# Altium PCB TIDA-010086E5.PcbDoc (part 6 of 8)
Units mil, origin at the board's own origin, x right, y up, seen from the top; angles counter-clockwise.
Board outline 6400 x 6200 mil, 6 copper layers (Top Layer, Power, AGND, Signal, PGND, Bottom Layer), stack 70.536 mil thick; 717 components, 376 nets, 2259 pads, 2183 vias.
Unrouted connection lines stored in the file: 1424.
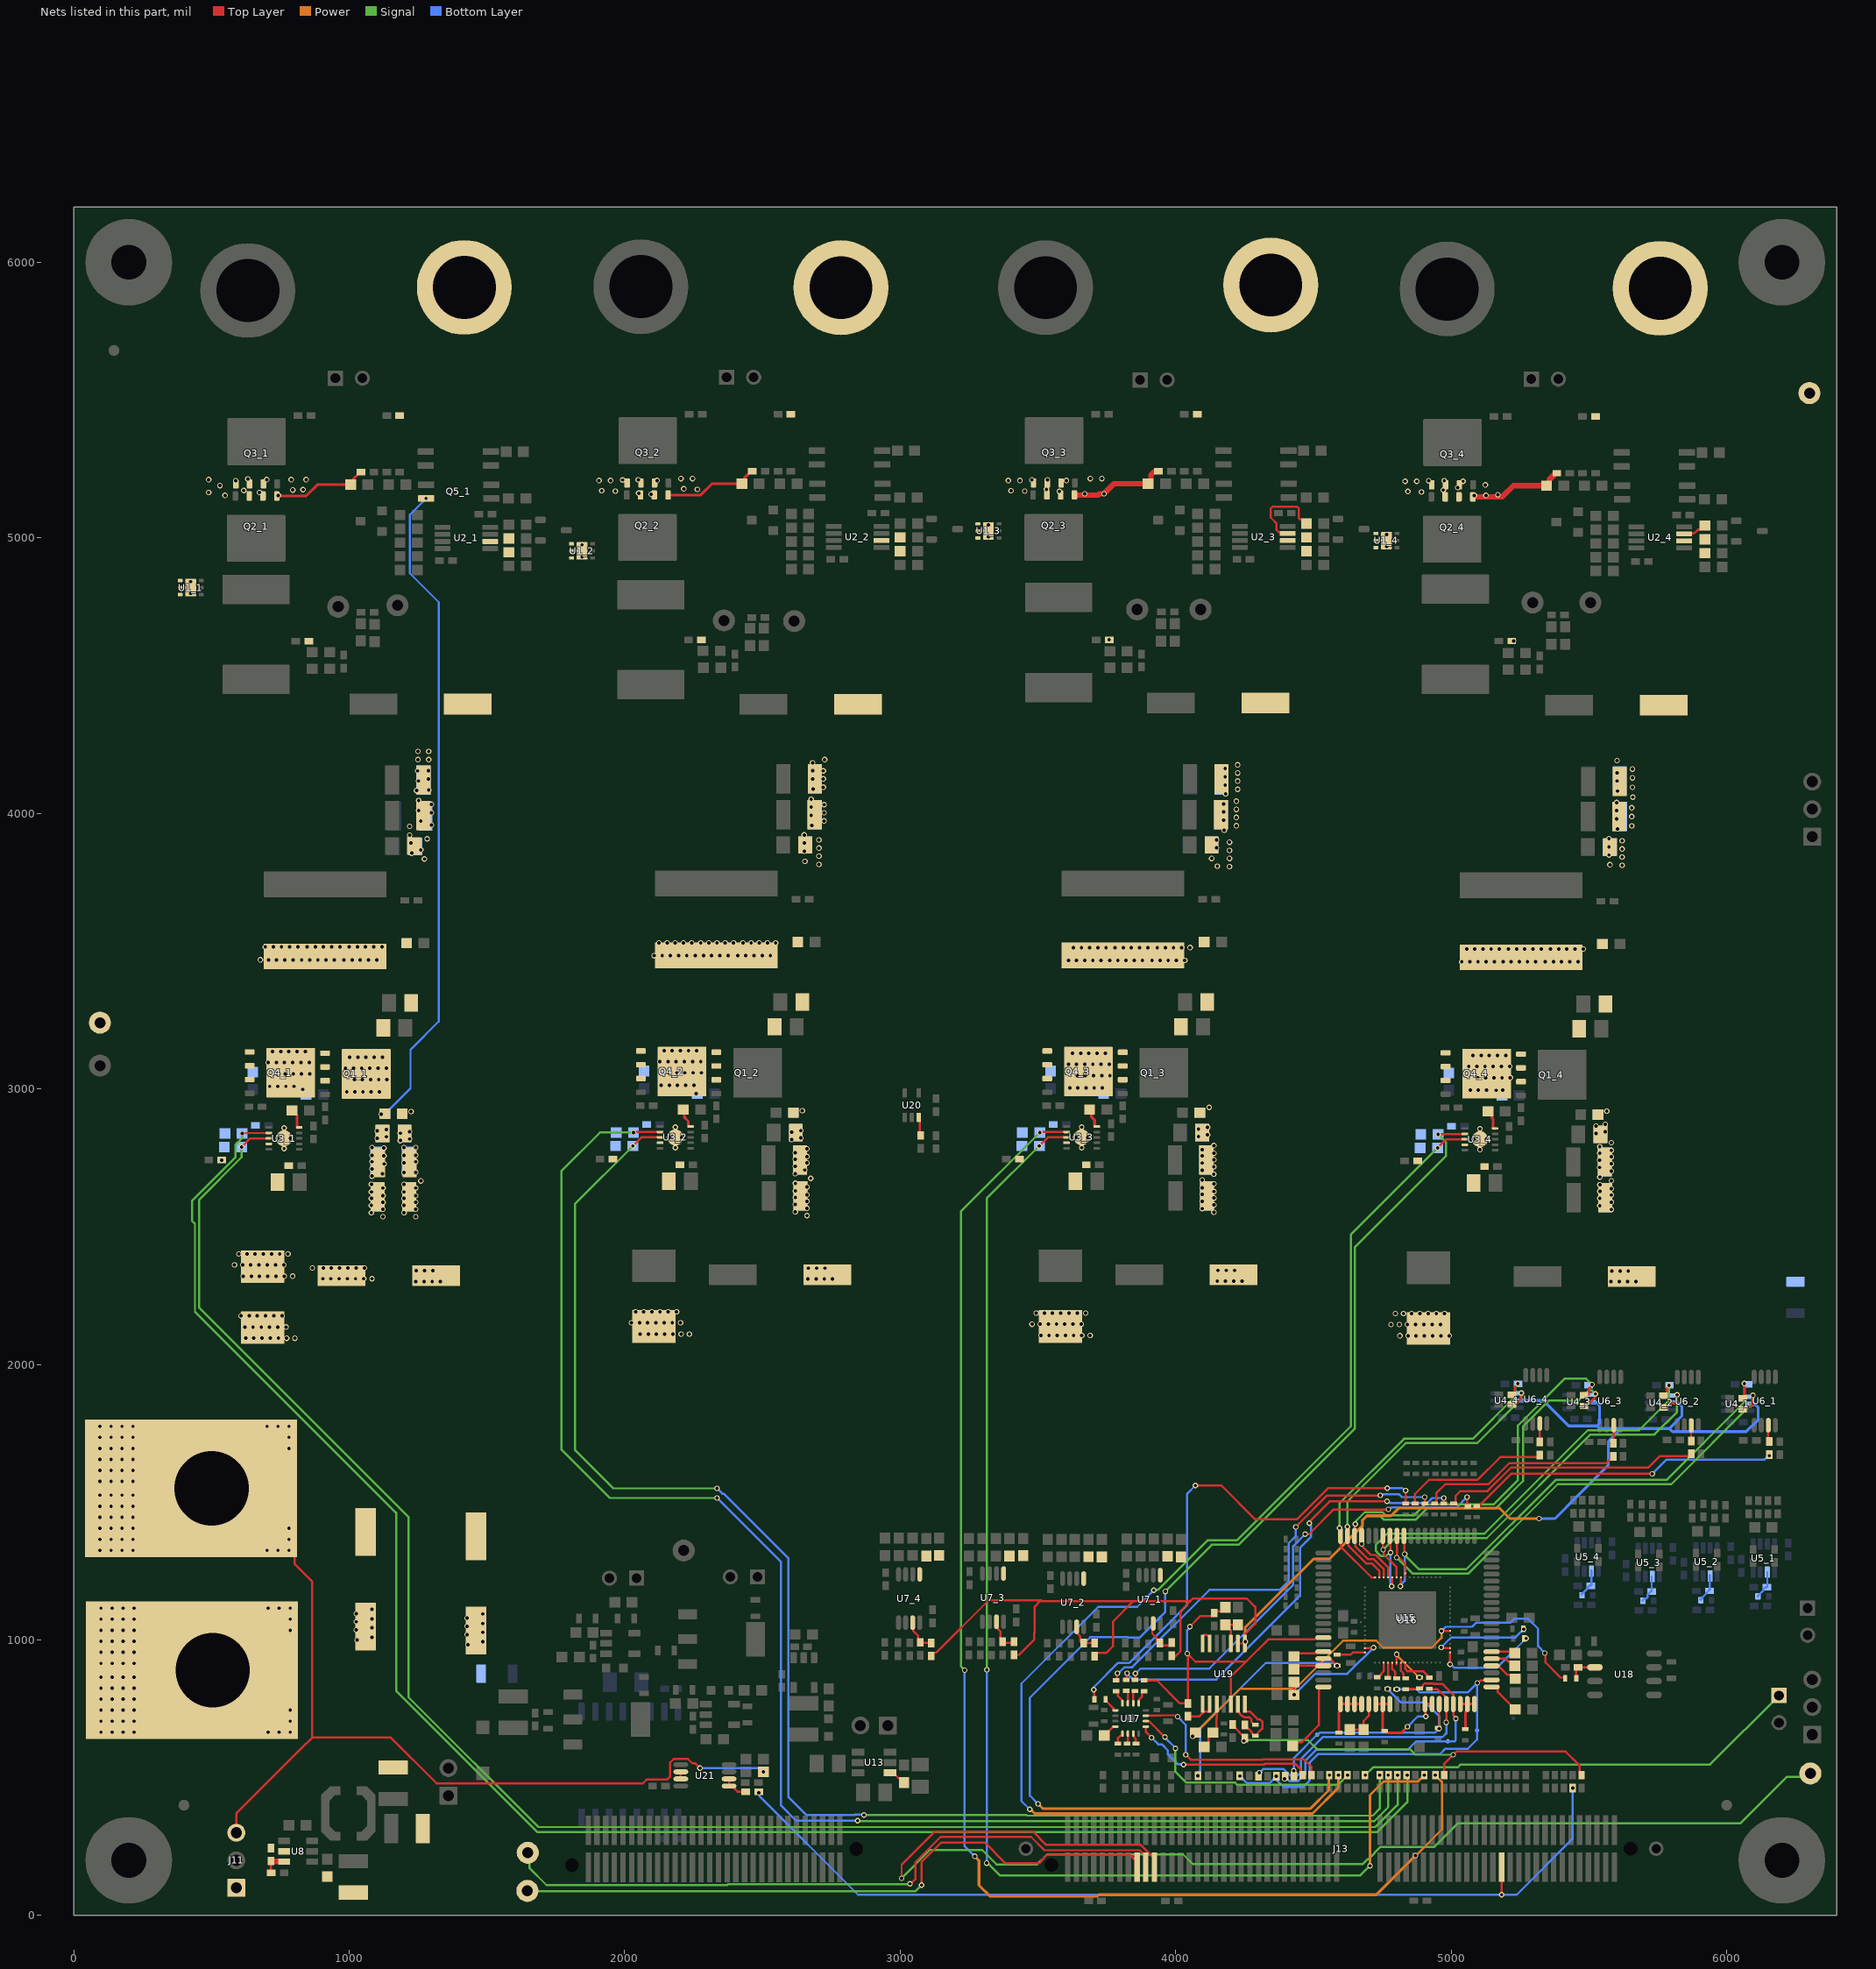
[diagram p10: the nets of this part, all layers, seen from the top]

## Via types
v1: diameter 20, hole 12.5, Top Layer to Bottom Layer, 1408 vias
v2: diameter 20, hole 12, Top Layer to Bottom Layer, tented both sides, 775 vias

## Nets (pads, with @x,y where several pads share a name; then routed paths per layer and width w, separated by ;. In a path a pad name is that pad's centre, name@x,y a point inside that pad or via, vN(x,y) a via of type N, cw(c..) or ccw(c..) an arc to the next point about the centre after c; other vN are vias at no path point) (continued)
NetR25_3_2: R25_3.2 U2_3.7 | length 311.6
  Top Layer w7.87: U2_3.7@4406.37,5015.63 4386.69,5015.63 4381.76,5020.55 4377.15,5020.55 4374.08,5020.55 4366.02,5028.61 4366.02,5051.52 4344.59,5072.94 4344.59,5106.35 4351.51,5113.27 4440.03,5113.27 4446.95,5106.35 4446.95,5070.72 4451.56,5066.1 4459.71,5066.1 R25_3.2@4474.47,5051.34
NetR25_4_2: R25_4.2 U2_4.7 | length 87.3
  Top Layer w7.87: U2_4.7@5845.27,5014.68 5858.04,5014.68 5858.67,5015.31 5881.01,5015.31 5895.56,5029.86 5905.61,5029.86 R25_4.2@5920.25,5044.5
NetR28_1_1: R28_1.1 R30_1.2 U2_1.6
NetR28_2_1: R28_2.1 R30_2.2 U2_2.6
NetR28_3_1: R28_3.1 R30_3.2 U2_3.6
NetR28_4_1: R28_4.1 R30_4.2 U2_4.6
NetR36_1_1: R36_1.1 R38_1.2 U5_1.6 | length 104.1
  Bottom Layer w7.87: R38_1.2@6113.13,1158.12 6113.13,1160.09 6134.51,1181.47 6134.51,1184.94 6141.32,1191.75 R36_1.1@6145.26,1191.75 6147.22,1193.72 U5_1.6@6147.22,1245.76
NetR36_2_1: R36_2.1 R38_2.2 U5_2.6 | length 102.9
  Bottom Layer w7.87: R38_2.2@5903.68,1146.83 5905.65,1146.83 5911.01,1152.19 5911.01,1154.16 5925.42,1168.57 5925.42,1170.07 5937.77,1182.42 U5_2.6@5937.77,1234.47
NetR36_3_1: R36_3.1 R38_3.2 U5_3.6 | length 106.6
  Bottom Layer w7.87: R38_3.2@5695.19,1142.03 5695.19,1144 5701.09,1149.9 5708.29,1149.9 5712.9,1154.51 5712.9,1165.18 5724.01,1176.28 5725.4,1176.28 5727.37,1178.25 U5_3.6@5727.37,1230.3
NetR36_4_1: R36_4.1 R38_4.2 U5_4.6 | length 104.1
  Bottom Layer w7.87: R38_4.2@5474.29,1164.49 5474.29,1166.46 5495.66,1187.83 5495.66,1191.3 5502.47,1198.11 5506.41,1198.11 5508.38,1200.08 U5_4.6@5508.38,1252.12
NetR44_1_1: R44_1.1 R46_1.2 U7_1.3 | length 132.4
  Top Layer w7.87: U7_1.3@3914.61,1053.97 3916.61,1051.96 3916.61,1038.41 3914.61,1036.4 3914.61,1022.94 3930.23,1007.32 3930.23,996.14 3934.93,996.14 R46_1.2@3942.54,988.53 3942.54,988.43 3950.41,980.56 3977.81,980.56 3985.69,988.43 R44_1.1@3985.69,989.68
NetR44_2_1: R44_2.1 R46_2.2 U7_2.3 | length 112.6
  Top Layer w7.87: U7_2.3@3640.26,1047.37 3642.14,1045.48 3642.14,1024.13 3653.68,1012.59 3653.68,993.89 3660.59,993.89 R46_2.2@3665.85,988.63 3704.96,988.67 R44_2.1@3705,988.63
NetR44_3_1: R44_3.1 R46_3.2 U7_3.3 | length 124.3
  Top Layer w7.87: U7_3.3@3346.12,1062.71 3346.12,1048.71 3354.23,1040.6 3354.23,1039.63 3363.69,1030.17 3363.69,1000.84 3375.23,989.3 3408.86,989.3 R44_3.1@3412.54,992.98
NetR44_4_1: R44_4.1 R46_4.2 U7_4.3 | length 124.2
  Top Layer w7.87: U7_4.3@3044.99,1062.71 3046.65,1061.05 3046.65,1033.18 3064.52,1015.3 3064.52,998.76 3073.97,989.3 3112.47,989.3 R44_4.1@3112.68,989.09
NetR45_1_2: R45_1.2 R47_1.1 U7_1.5
NetR45_2_2: R45_2.2 R47_2.1 U7_2.5
NetR45_3_2: R45_3.2 R47_3.1 U7_3.5
NetR45_4_2: R45_4.2 R47_4.1 U7_4.5
NetR49_1_1: R49_1.1 U6_1.7 | length 67
  Top Layer w7.87: R49_1.1@6149.41,1708.04 U6_1.7@6149.41,1775
NetR49_2_1: R49_2.1 U6_2.7 | length 67
  Top Layer w7.87: R49_2.1@5870.55,1715.22 U6_2.7@5870.55,1782.18
NetR49_3_1: R49_3.1 U6_3.7 | length 67
  Top Layer w7.87: R49_3.1@5590.55,1715.22 U6_3.7@5590.55,1782.18
NetR49_4_1: R49_4.1 U6_4.7 | length 66.9
  Top Layer w7.87: R49_4.1@5321.48,1718.51 U6_4.7@5321.48,1785.42
NetR53_1: R53.1 R54.2 U8.3 | length 89.5
  Top Layer w7.87: R54.2@715.84,197.48 715.84,155.54 R53.1@716.38,155
  Top Layer w20: R54.2@716.98,196.34 762.2,196.34 U8.3@763.34,195.2
NetR63_1: R63.1 U13.4 | length 65.9
  Top Layer w7.87: U13.4@2963.07,517.6 2973.9,517.6 2993.47,498.03 2999.01,498.03 3013.77,483.26 R63.1@3013.77,482.28
NetR65_1: R65.1 U15.37 | length 64.7
  Top Layer w7.87: U15.37@4785.93,917.41 4785.93,894.23 4796.33,883.82 4796.33,864.14 4799.9,860.58 R65.1@4801.97,860.58
NetR66_1: R66.1 U15.36 | length 56.5
  Top Layer w7.87: R66.1@4768.67,862.04 4770.73,864.09 4770.73,879.19 4770.18,879.74 U15.36@4770.18,917.41
NetR67_1: R67.1 U15.38 | length 158.6
  Top Layer w7.87: 4801.67,912.11 U15.38@4801.67,917.82 v2(4801.67,947.69) ; R67.1@4883.57,866.3 4883.57,864.8 v2(4884.57,863.8)
  Power w7.87: v2@4799.24,947.69 4883.12,863.8 v2(4884.57,863.8)
NetR68_1: R68.1 U15.35 | length 65.7
  Top Layer w7.87: R68.1@4730.96,864.49 4735.46,864.49 4744.86,873.89 4744.86,876.36 4754.43,885.93 U15.35@4754.43,917.82
NetR69_2: R69.2 U16.40 | length 279.3
  Top Layer w7.87: R69.2@4424.15,614.55 4437.85,628.25 4456.94,628.25 4519.19,690.5 4519.19,824.7 4523.74,829.24 U16.40@4535.93,829.24
NetR71_1: R71.1 U16.41 U16.42 U16.43 U16.44 | length 183.1
  Top Layer w10: R71.1@4591.96,663.38 4591.96,738.51 4597.93,744.48 U16.41@4597.93,767.23 U16.42@4623.52,767.23 U16.43@4649.11,767.23 U16.44@4674.7,767.23
NetR73_1: R73.1 U15.40 | length 125.2
  Top Layer w7.87: U15.40@4833.17,915.86 4833.17,894.23 4841.79,885.61 4898.96,885.61 4911.72,872.85 4911.72,866.24 4915.28,862.68 R73.1@4919.78,862.68
NetR74_1: R74.1 U15.49 | length 378.6
  Top Layer w7.87: v2(4995.49,911.16) 4995.57,911.24 U15.49@4995.57,954.24 ; R74.1@5262.81,1008.11 5265.53,1005.39 v2(5271.82,1005.39)
  Bottom Layer w7.87: v2(4995.49,911.16) 4998.77,911.16 5010.62,899.31 5030.38,899.31 5030.63,899.07 5165.5,899.07 v2(5271.82,1005.39)
NetR75_1: R75.1 U16.46 U16.47 U16.48 U16.53 U16.54 | length 403.4
  Top Layer w7.87: U16.53@4905.02,767.23 4906.48,765.77 4906.48,723.71 v2(4907.95,722.24)
  Top Layer w10: U16.46@4725.89,767.23 U16.47@4751.48,767.23 ; U16.48@4777.07,767.23 U16.47@4751.48,767.23 ; v2(4841.04,685) 4818.52,662.48 4769.79,662.48 4762.87,669.4 4753.98,669.4 4751.48,671.9 U16.47@4751.48,767.23 ; U16.53@4905.02,767.23 U16.54@4930.61,767.23
  Bottom Layer w7.87: v2(4841.04,685) 4878.28,722.24 v2(4907.95,722.24)
NetR76_1: R76.1 U15.50 | length 362.9
  Top Layer w7.87: v2(4963.44,972.43) 4965.77,970.11 4974.17,970.11 4974.28,969.99 U15.50@4995.57,969.99 ; R76.1@5261.76,1040.85 5261.76,1040.37 v2(5263.2,1038.94)
  Bottom Layer w7.87: v2(4963.44,972.43) 4999.89,1008.88 5233.14,1008.88 v2(5263.2,1038.94)
NetR78_1: R78.1 U15.32 | length 104.1
  Top Layer w7.87: R78.1@4585.69,946.36 4634.91,946.36 4642.79,954.24 U15.32@4686.52,954.24
NetR79_1: R79.1 U16.58 U16.59 U16.60 | length 145.6
  Top Layer w10: U16.58@5032.97,767.23 U16.59@5058.56,767.23 ; R79.1@5051.1,675.86 5051.1,737.01 5058.56,744.48 U16.59@5058.56,767.23 ; U16.60@5084.15,767.23 U16.59@5058.56,767.23
NetR80_2: R80.2 U16.61 | length 117.4
  Top Layer w7.87: U16.61@5156.53,829.24 5164.17,829.24 5168.71,824.7 5168.71,810.08 5230.72,748.07 R80.2@5231.7,748.07
NetR81_2: R81.2 U16.37 | length 111.7
  Top Layer w7.87: R81.2@4429.41,893.58 4441.85,906.01 U16.37@4535.93,906.01
NetR84_2: R84.2 U16.64 | length 105
  Top Layer w7.87: U16.64@5146.16,906.01 5169.49,906.01 5174.42,901.09 5175.39,901.09 5202.71,873.77 5216.94,873.77 R84.2@5231.7,859.01
NetR85_2: R85.2 U16.65 | length 95
  Top Layer w7.87: U16.65@5146.16,931.6 5195.71,931.6 5205.81,921.5 5210.15,921.5 5210.87,920.78 5215.75,920.78 R85.2@5230.51,906.01
NetR86_2: R86.2 U16.66 | length 82.1
  Top Layer w7.87: U16.66@5146.16,957.19 5217.19,957.2 R86.2@5225,965
NetR90_2: R90.2 R93.1 U15.31 | length 438.3
  Top Layer w7.87: v2(4429.41,800.57) R93.1@4429.41,847.14 ; U15.31@4686.52,969.99 4716.33,969.99 v2(4718.02,971.69)
  Bottom Layer w7.87: v2(4429.41,800.57) 4505.83,876.98 4622.36,876.98 4673.64,928.27 4674.61,928.27 v2(4718.02,971.69)
NetR98_1: R98.1 U16.35 | length 113.6
  Top Layer w7.87: R98.1@4429.41,940.15 4439.96,950.7 4505.12,950.7 4509.73,955.31 4534.04,955.31 U16.35@4535.93,957.19
NetR100_2: R100.2 U17.2 | length 48.3
  Top Layer w7.87: U17.2@3845.85,770 3845.85,812.5 3848.35,815 R100.2@3850.64,815
NetR101_2: R101.2 U17.3 | length 49.7
  Top Layer w7.87: R101.2@3820,815 3823.66,815 3826.16,812.5 U17.3@3826.16,770
NetR102_2: R102.2 U17.4 | length 51.8
  Top Layer w7.87: R102.2@3790,815 3790,796.6 3806.18,780.42 3806.18,770.3 U17.4@3806.48,770
NetR103_2: R103.2 U17.5 | length 59.3
  Top Layer w7.87: R103.2@3745,785 3748.56,781.44 3748.56,776.73 3773.53,751.77 3773.53,745.13 3774.25,744.41 U17.5@3780.89,744.41
NetR104_1: R104.1 U17.1 | length 51.1
  Top Layer w7.87: U17.1@3865.53,770 3865.81,770.27 3865.81,782.04 3877.89,794.13 3877.89,812.71 R104.1@3880.18,815
NetR105_1: R105.1 U17.10 | length 36.9
  Top Layer w7.87: R105.1@3823.61,623.97 3823.66,623.97 3826.16,626.47 U17.10@3826.16,659.76
NetR106_1: R106.1 U17.9 | length 46.9
  Top Layer w7.87: R106.1@3790.35,623.38 3790.35,643.64 3799.67,652.95 3806.2,652.95 3806.48,653.22 U17.9@3806.48,659.76
NetR107_1: R107.1 U17.11 | length 40.3
  Top Layer w7.87: U17.11@3845.85,659.76 3845.85,652.25 3849,649.1 3849,645.82 3855.35,639.47 R107.1@3855.35,623.38
NetR108_1: R108.1 U17.8 | length 54.2
  Top Layer w7.87: R108.1@3740,653.22 3740.98,653.22 3772.84,685.07 3780.61,685.07 U17.8@3780.89,685.35
NetR109_1: R109.1 R112.2 U18.6 | length 103.7
  Top Layer w7.87: R109.1@5453.64,860.5 5453.64,893.69 5460.45,900.5 R112.2@5460.88,900.5 U18.6@5521.35,900.5
NetR110_2: R110.2 R113.2 U19.3 | length 174.9
  Top Layer w7.87: R113.2@4102.74,611.84 4103.72,611.84 4118.48,626.6 4118.48,648.51 4133.25,663.27 R110.2@4134.23,663.27 4147.98,677.02 4147.98,715.79 4148.64,716.45 U19.3@4148.64,766.6
NetR111_1: R111.1 U19.1 U19.2 | length 141.1
  Top Layer w7.87: R111.1@4043.58,722.51 4085.89,722.51 U19.1@4103.48,740.11 ; U19.1@4097.46,766.6 4097.46,746.13 U19.1@4103.48,740.11 ; U19.2@4123.05,766.6 4123.05,742 4121.16,740.11 U19.1@4103.48,740.11
NetR114_1: R114.1 R116.1 U19.10 | length 121.6
  Top Layer w7.87: U19.10@4199.82,987.07 4199.82,1034.19 4180,1054.02 R114.1@4180,1055 R116.1@4225.41,1055
NetR115_1: R115.1 R117.2 U19.7 | length 223.7
  Top Layer w7.87: R115.1@4251,690.9 4251,686.96 4258.88,679.08 4262.81,679.08 4276.14,665.76 4276.14,660.34 4280.76,655.73 4284.08,655.73 4287.64,652.16 4313.92,678.44 4313.92,703.31 4305.76,711.47 4297.48,711.47 4268.84,740.11 4252.89,740.11 4251,742 U19.7@4251,766.6
NetR117_1: R117.1 U19.6 | length 112.2
  Top Layer w7.87: U19.6@4225.41,766.6 4228.37,763.65 4228.37,737.88 4232.3,733.95 4232.3,731.38 4240.39,723.3 4242.95,723.3 4247.79,718.45 4267.71,718.45 4274.63,711.54 4274.63,701.9 4284.36,692.16 R117.1@4284.51,692.16
NetR122_2: R122.2 U20.3 | length 68.2
  Top Layer w7.87: U20.3@3067.45,2896.18 3070.32,2893.3 3070.32,2834.4 R122.2@3073.99,2830.73
NetR143_1: R143.1 U21.1 U21.2 | length 97.6
  Top Layer w7.87: U21.2@2378.7,495.59 U21.1@2378.7,470 2394.33,470 2397.89,466.44 2397.89,460.88 2409.59,449.18 R143.1@2438.88,449.18
NetR179_1: R179.1 U15.39 | length 65.1
  Top Layer w7.87: U15.39@4817.42,915.86 4817.42,887.71 4826.61,878.52 4826.61,864.14 4830.18,860.58 R179.1@4834.68,860.58
NetU19_13: U19.13 U19.14 | length 80.3
  Top Layer w7.87: U19.14@4097.46,987.07 4097.46,1011.68 4104.06,1018.28 4112.34,1018.28 4117.05,1013.57 4121.16,1013.57 4123.05,1011.68 U19.13@4123.05,987.07
NetU21_6: U21.6 U21.7 | length 25.6
  Top Layer w7.87: U21.7@2203.5,495.59 U21.6@2203.5,521.18
PGND: C1.2 C2.2 C3_1.2 C3_2.2 C3_3.2 C3_4.2 C4_1.2 C4_2.2 C4_3.2 C4_4.2 C5_1.2 C5_2.2 C5_3.2 C5_4.2 C6_1.2 C6_2.2 C6_3.2 C6_4.2 C7_1.2 C7_2.2 C7_3.2 C7_4.2 C8_1.2 C8_2.2 C8_3.2 C8_4.2 C9_1.2 C9_2.2 C9_3.2 C9_4.2 C10_1.2 C10_2.2 C10_3.2 C10_4.2 C11_1.2 C11_2.2 C11_3.2 C11_4.2 C12_1.2 C12_2.2 C12_3.2 C12_4.2 C13_1.2 C13_2.2 C13_3.2 C13_4.2 C14_1.2 C14_2.2 C14_3.2 C14_4.2 C15_1.2 C15_2.2 C15_3.2 C15_4.2 C16_1.2 C16_2.2 C16_3.2 C16_4.2 C17_1.2 C17_2.2 C17_3.2 C17_4.2 C18_1.2 C18_2.2 C18_3.2 C18_4.2 C19_1.2 C19_2.2 C19_3.2 C19_4.2 C21_1.2 C21_2.2 C21_3.2 C21_4.2 C22_1.1 C22_2.1 C22_3.1 C22_4.1 C26_1.1 C26_2.1 C26_3.1 C26_4.1 C27_1.2 C27_2.2 C27_3.2 C27_4.2 C41.2 C42.2 C43.2 C44.2 J2.1 J9_1.1 J9_2.1 J9_3.1 J9_4.1 J11.1 Q4_1.1 Q4_1.2 Q4_1.3 Q4_2.1 Q4_2.2 Q4_2.3 Q4_3.1 Q4_3.2 Q4_3.3 Q4_4.1 Q4_4.2 Q4_4.3 R7_1.1 R7_2.1 R7_3.1 R7_4.1 R9_1.1 R9_2.1 R9_3.1 R9_4.1 R11_1.1 R11_2.1 R11_3.1 R11_4.1 R23_1.1 R23_2.1 R23_3.1 R23_4.1 R24_1.1 R24_2.1 R24_3.1 R24_4.1 R54.1 R55.2 R56.1 T2.1 TP3.1 TP4.1 U1_1.1 U1_1.2 U1_1.3 U1_1.7@424.52,4819.36 U1_2.1 U1_2.2 U1_2.3 U1_2.7@1845,4952.72 U1_3.1 U1_3.2 U1_3.3 U1_3.7@3320,5025 U1_4.1 U1_4.2 U1_4.3 U1_4.7@4765,4990 U3_1.9 U3_1.11 U3_2.9 U3_2.11 U3_3.9 U3_3.11 U3_4.9 U3_4.11 U8.2
  other v1: 1430.73,982.88 1484.89,993.48 1028.26,999.17 1082.42,1009.77 1428.18,1019.47 1484.89,1027.63 1025.71,1035.76 1082.42,1043.92 1428.18,1049.47 1484.89,1059.47 1025.71,1065.76 1082.42,1075.76 1428.18,1078.6 1484.89,1094.47 1025.71,1094.89 1082.42,1110.76 5580,2300 5610,2300 5640,2300 5670,2300 1241.06,2300.85 1271.06,2300.85 1301.06,2300.85 1331.06,2300.85 4150.71,2301.92 4180.71,2301.92 4210.71,2301.92 4240.71,2301.92 2664.41,2309.91 2694.41,2309.91 2724.41,2309.91 2754.41,2309.91 5582.24,2339.15 5612.24,2339.15 5642.24,2339.15 1243.31,2340 1273.31,2340 1303.31,2340 4152.95,2341.07 4182.95,2341.07 4212.95,2341.07 2666.65,2349.06 2696.65,2349.06 2726.65,2349.06 1241.23,2536.2 2661.35,2539.78 1198.91,2550 4138.23,2551.49 2619.03,2553.58 5581.18,2562.22 1241.23,2562.86 4095.92,2565.29 2661.35,2566.45 5538.86,2576.02 1198.91,2576.66 4138.23,2578.15 2619.03,2580.25 1241.48,2588.51 5581.18,2588.88 2661.59,2592.1 4095.92,2591.95 1199.16,2602.31 5538.86,2602.68 4138.48,2603.8 2619.28,2605.89 1241.48,2611.94 5581.42,2614.53 2661.59,2615.52 4096.17,2617.6 1199.16,2625.74 4138.48,2627.23 5539.11,2628.33 2619.28,2629.32 5581.42,2637.95 1241.48,2640 4096.17,2641.02 2661.59,2643.58 5539.11,2651.75 1199.16,2653.8 4138.48,2655.29 2619.28,2657.38 1260,2665.73 5581.42,2666.02 4096.17,2669.08 2675,2675 5539.11,2679.81 4137.98,2690.29 2618.78,2692.38 1198.67,2696.98 1241.23,2697.05 5580.93,2701.02 4095.67,2704.08 2653.54,2705.25 5538.61,2714.81 4137.98,2716.95 2618.78,2719.04 5580.93,2727.68 1198.67,2731.37 2661.35,2730.89 4095.67,2730.75 1241.23,2735.5 5538.61,2741.48 4138.23,2742.6 2619.03,2744.69 5581.18,2753.33 2661.35,2754.32 4095.92,2756.4 1198.67,2758.92 1241.23,2758.92 4138.23,2766.02 5538.86,2767.13 2619.03,2768.12 5581.18,2776.75 4095.92,2779.82 2661.35,2782.38 1198.67,2786.73 1241.23,2786.98 5538.86,2790.55 4138.23,2794.08 5581.18,2804.81 1185.41,2812.2 2605.53,2815.79 1218.59,2818.07 2638.71,2821.65 4082.41,2827.49 4115.59,2833.35 5525.35,2838.22 1185.41,2838.87 2605.53,2842.45 5558.54,2844.08 1218.59,2844.73 2638.71,2848.31 4082.41,2854.15 4115.59,2860.01 5525.35,2864.88 5558.54,2870.74 1224.47,2917.39 5564.48,2918.88 2644.59,2920.98 4121.48,2932.68 4195,3806.18 4150.84,3808.29 5620,3811.3 5575.84,3813.41 2705,3814.61 2654.19,3825.65 1272.66,3834.35 4130.21,3836.18 4195,3836.18 5620,3841.3 2705,3844.61 5572.3,3848.68 1226.76,3855.35 2651.64,3862.24 4195,3865.31 1259.68,3867.25 5620,3870.44 2705,3873.74 4148.08,3874.88 5572.3,3878.68 1224.21,3891.94 2651.64,3892.24 4195,3895 5620,3900.12 2705,3903.43 4148.08,3904.01 1282.66,3907.38 5572.3,3907.81 1219.31,3920.55 2651.64,3921.38 4175.84,3938.29 5602.76,3943.41 1219.31,3952.49 5655,3954.01 4219.99,3955 2679.19,3955.65 1298.83,3957.4 1259.68,3972.06 2723.35,3972.37 4173.28,3974.88 5600.21,3980 4219.99,3985 5655,3988.16 2676.64,3992.24 1298.83,4002.06 2723.35,4002.37 4173.28,4004.88 1251.86,4010.12 5600.21,4010 4219.99,4014.13 5655,4020 2676.64,4022.24 1298.83,4032.06 2723.35,4031.5 4173.28,4034.01 5600.21,4039.13 4219.99,4043.82 1251.86,4046.69 2676.64,4051.38 5659.05,4058.43 4180.84,4070.32 5603.68,4080.78 1244.3,4082.49 1288.41,4084.35 4225,4087.03 2684.19,4087.68 2720.74,4094.87 5657.3,4094.54 4179.39,4102.87 1250.86,4117.38 4225,4117.03 5601.13,4117.37 2681.64,4124.27 1287.41,4124.57 2720.74,4124.87 5657.3,4128.69 4179.39,4132.87 4225,4146.16 5601.13,4147.37 1248.31,4153.97 2681.64,4154.27 2720.74,4154.01 1287.41,4154.57 5657.3,4160.53 4179.39,4162.01 4225,4175.85 2681.64,4183.41 5601.73,4191.35 1249.31,4195 1288.41,4195 2725.67,4195 1249.31,4225 1288.41,4225
  other v2: 99.28,665 139.28,665 179.28,665 219.28,665 705.55,665 745.55,665 785.55,665 99.28,705 139.28,705 179.28,705 219.28,705 785.55,705 99.28,745 139.28,745 179.28,745 219.28,745 785.55,745 99.28,785 139.28,785 179.28,785 219.28,785 99.28,825 139.28,825 179.28,825 219.28,825 99.28,865 139.28,865 179.28,865 219.28,865 99.28,915 139.28,915 179.28,915 219.28,915 99.28,955 139.28,955 179.28,955 219.28,955 99.28,995 139.28,995 179.28,995 219.28,995 99.28,1035 139.28,1035 179.28,1035 219.28,1035 785.55,1035 99.28,1075 139.28,1075 179.28,1075 219.28,1075 785.55,1075 99.28,1115 139.28,1115 179.28,1115 219.28,1115 705.55,1115 745.55,1115 785.55,1115 537.24,2741.42 5104.32,2779.58 763.43,2782.83 2183.54,2786.42 3658.54,2786.42 5081.69,2816.98 5126.96,2816.98 740.79,2820.24 786.06,2820.24 2160.91,2823.82 2206.18,2823.82 3635.91,2823.82 3681.18,2823.82 5104.32,2854.38 763.43,2857.64 2183.54,2861.22 3658.54,2861.22 5226.12,4625.15 3757.73,4630 424.52,4797.7 424.52,4841.01 1845,4931.06 4765,4968.35 1845,4974.37 3320,5003.35 4765,5011.65 3320,5046.65
PWM_HO1: R24_1.2 R130.1 U3_1.7 | length 6530.2
  Top Layer w7.87: v2(611.5,2837.83) 613.31,2839.65 708.03,2839.65 U3_1.7@708.31,2839.92 ; R130.1@4838,509.13 v2(4840.25,509.13)
  Signal w7.87: v2(611.5,2837.83) 611.5,2821.91 587.71,2798.12 587.71,2752.16 429.25,2593.7 429.25,2520.77 440,2510.02 440,2191.45 1170,1461.45 1170,815 1682.14,302.86 4731.81,302.86 4840.25,411.3 v2(4840.25,509.13)
PWM_HO2: R24_2.2 R134.1 U3_2.7 | length 5643.4
  Top Layer w7.87: v2(2031.61,2841.42) 2033.42,2843.23 2128.15,2843.23 U3_2.7@2128.43,2843.5
  Top Layer w20: v2(4770.96,509.13) R134.1@4772.07,509.13
  Signal w7.87: v2(2031.61,2841.42) 1910.12,2841.42 1770,2701.3 1770,1691.37 1946.37,1515 v2(2335,1515) ; v2(2845,343.61) 2846.49,342.13 4720.51,342.13 4770.96,392.57 v2(4770.96,509.13)
  Bottom Layer w7.87: v2(2335,1515) 2567.11,1282.89 2567.11,398.96 2622.46,343.61 v2(2845,343.61)
PWM_HO3: R24_3.2 R131.2 U3_3.7 | length 4980.2
  Top Layer w7.87: v2(3506.61,2841.42) 3508.42,2843.23 3603.15,2843.23 U3_3.7@3603.43,2843.5
  Signal w7.87: v2(3233.77,890) 3220,903.77 3220,2554.8 v2(3506.61,2841.42)
  Power w7.87: v2(4870,217.27) 4871.55,217.27 4966.28,312 4966.28,484.75 v2(4941.9,509.13)
  Power w10: v2(3270.29,214.63) 3285.66,199.26 3285.66,109.34 3325,70 3715.66,70 3720.66,75 4728.03,75 4870,216.97 v2(4870,217.27)
  Bottom Layer w7.87: v2(3233.77,890) 3233.77,251.14 v2(3270.29,214.63)
PWM_HO4: R24_4.2 R139.2 U3_4.7 | length 4488.3
  Top Layer w7.87: R139.2@4557,509.13 v2(4557.89,509.13) ; v2(4952.39,2834.58) 4954.2,2836.39 5048.93,2836.39 U3_4.7@5049.2,2836.67
  Signal w7.87: v2(3962.04,1175.94) 3962.04,1176.75 4130.55,1345.26 4227.57,1345.26 4650.75,1768.44 4650.75,2425.75 4981.57,2756.57 4981.57,2805.4 v2(4952.39,2834.58)
  Power w10: v2(3500,405) 3517.13,387.87 4489.09,387.87 4555.59,454.37 4555.59,506.83 v2(4557.89,509.13)
  Bottom Layer w7.87: v2(3500,405) 3470,435 3470,789.83 3690.24,1010.07 3825.35,1010.07 3826.58,1008.85 3869.75,1008.85 3962.04,1101.15 3962.04,1175.71 v2@3961.93,1175.83
PWM_LO1: R23_1.2 R132.1 U3_1.8 | length 6414.5
  Top Layer w7.87: v2(609.52,2789.08) 640.67,2820.24 U3_1.8@708.31,2820.24 ; R132.1@4804.07,509.13 v2(4805.31,509.13)
  Signal w7.87: v2(609.52,2789.08) 609.52,2751.7 455.75,2597.93 455.75,2205.47 1215,1446.21 1215,792.27 1686.53,320.74 4724.4,320.74 4805.31,401.64 v2(4805.31,509.13)
PWM_LO2: R23_2.2 R136.1 U3_2.8 | length 5413.9
  Top Layer w7.87: v2(2029.64,2792.67) 2060.79,2823.82 U3_2.8@2128.43,2823.82 ; R136.1@4740.07,509.13 v2(4740.19,509.13)
  Signal w7.87: v2(2029.64,2792.67) 1819.02,2582.05 1819.02,1689.46 1958.48,1550 v2(2335,1550) ; v2(2867.95,364.61) 2868.34,365 3457.65,365 3460.53,362.13 4715.24,362.13 4740.19,387.08 v2(4740.19,509.13)
  Bottom Layer w7.87: v2(2335,1550) 2354.36,1530.64 2359.48,1530.64 2594.14,1295.99 2594.14,429.35 2658.49,365 2835.54,365 2835.97,365.42 2867.14,365.42 v2(2867.95,364.61)
PWM_LO3: R23_3.2 R133.2 U3_3.8 | length 4701.5
  Top Layer w7.87: v2(3504.64,2792.67) 3535.79,2823.82 U3_3.8@3603.43,2823.82
  Signal w7.87: v2(3313.6,190) 3316.85,190 3361.34,145.51 4670.08,145.51 v2(4704.92,180.35) ; v2(3314.05,891.66) 3314.05,2602.07 v2(3504.64,2792.67)
  Power w10: v2(4704.92,180.35) 4704.92,436.98 4754.19,486.25 4879.47,486.25 4902,508.78 v2(4902,509.13)
  Bottom Layer w7.87: v2(3313.6,190) 3313.82,190.22 3313.82,891.43 v2(3314.05,891.66)
PWM_LO4: R23_4.2 R138.2 U3_4.8 | length 4514.3
  Top Layer w7.87: v2(4950.42,2785.83) 4981.57,2816.98 U3_4.8@5049.2,2816.98
  Signal w7.87: v2(3919.8,1179.93) 3921.11,1181.25 3935.25,1181.25 4115.01,1361 4221.04,1361 4635,1774.96 4635,2470.41 4734.06,2569.47 v2(4950.42,2785.83)
  Power w10: v2(3470,385) 3472.71,385 3487.71,370 4496.49,370 4590,463.51 v2(4590,509.13)
  Bottom Layer w7.87: v2(3470,385) 3440,415 3440,841.42 3718.49,1119.91 3859.78,1119.91 v2(3919.8,1179.93)
REF1V25: R44_1.2 R44_2.2 R44_3.2 R44_4.2 U4_1.5 U4_2.5 U4_3.5 U4_4.5 U19.8 U19.9 | length 5288.5
  Top Layer w7.87: R44_4.2@3112.68,941.85 3112.68,945.79 3120.55,953.66 3130.57,953.66 3320.74,1143.83 3507.89,1143.83 3510.8,1143.83 3507.89,1140.92 ; R44_3.2@3412.54,945.74 3431.55,945.74 3486.68,1000.88 3486.68,1024.92 3487.84,1026.08 3487.84,1120.87 3507.89,1140.92 ; R44_2.2@3705,941.38 3705,944.3 3712.87,952.17 3747.39,952.17 3772.2,976.97 3772.2,1066.53 3846.59,1140.92 ; R44_1.2@3985.69,942.43 3985.69,938.74 3997.11,938.74 4017.18,958.82 4017.18,1104.86 4053.24,1140.92 ; U19.9@4225.41,987.07 U19.8@4251,987.07 ; v2(4252.19,993.61) 4252.89,993.61 4252.89,1022.88 4288.33,1058.32 4288.33,1119.46 4257.88,1149.91 4062.23,1149.91 4053.24,1140.92 ; 3507.89,1140.92 3510.8,1140.92 3846.59,1140.92 ; 3846.59,1140.92 4053.24,1140.92
  Power w10: v2(4252.19,993.61) 4252.19,1046.09 4500.19,1294.1 4557.75,1294.1 4677.37,1413.71 4677.37,1434.08 4693.73,1450.45 4781.16,1450.45 4808.59,1477.87 5175.45,1477.87 5212.87,1440.46 v2(5319.03,1440.46)
  Bottom Layer w10: U4_4.5@5245.93,1868.83 5333.52,1868.83 5425.58,1776.77 5528.44,1776.77 ; v2(5319.03,1440.46) 5376.34,1440.46 5454.56,1518.68 5454.56,1518.8 5569.6,1633.84 5569.6,1719.53 5617.33,1767.26 ; U4_3.5@5507.73,1863.89 5510.6,1861.02 5527.66,1861.02 5538.61,1850.06 5538.61,1786.94 5528.44,1776.77 ; U4_2.5@5806.26,1861 5809.14,1858.13 5826.19,1858.13 5836.85,1847.46 5836.85,1812.46 5791.65,1767.26 ; U4_1.5@6083.61,1856.62 6086.49,1853.75 6103.54,1853.75 6114.2,1843.08 6114.2,1799.31 6070.6,1755.71 5803.2,1755.71 5791.65,1767.26 ; 5528.44,1776.77 5537.95,1767.26 5617.33,1767.26 ; 5617.33,1767.26 5791.65,1767.26
REF2V5: C88.1 R104.2 R111.2 R114.2 U16.33 U19.5 | length 1356.8
  Top Layer w7.87: R104.2@3881.79,853.39 3931.43,853.39 4015.07,769.75 R111.2@4043.58,769.75 v2@4043.58,948.44 ; v2(4041.72,950.31) 4042.02,950.31 4071.2,921.12 4255.23,921.12 ; v2(4051.3,1048.19) 4089.85,1086.73 4133.19,1086.73 4140,1093.54 C88.1@4140,1097.48 4146.81,1104.29 4166.3,1104.29 R114.2@4180,1117.99 ; U19.5@4199.82,766.6 4199.82,865.72 4255.23,921.12 ; U16.33@4535.93,1008.38 4512.59,1008.38 4507.67,1003.45 4506.69,1003.45 4504.73,1001.49 4335.59,1001.49 4255.23,921.12
  Bottom Layer w7.87: v2(4041.72,950.31) 4041.72,1035.36 4051.3,1044.94 v2(4051.3,1048.19)
REF2V5_C2K: C91.1 R115.2 R123.1 R129.2 | length 1475.9
  Top Layer w7.87: C91.1@4206.6,693.02 4206.6,689.08 4214.47,681.21 4215.43,681.21 4230.22,666.42 4230.22,664.52 4239.28,655.46 4243.13,655.46 4251,647.59 R115.2@4251,643.65 4251,637.58 v2(4246.96,633.53) ; R129.2@4974.07,509.13 4974.07,549.83 v2(5007.38,583.14) 5019.24,595 5414.39,595 5466.19,543.2 5466.19,515.94 R123.1@5473,509.13
  Signal w7.87: v2(4246.96,633.53) 4249.28,635.85 4257.12,635.85 4257.63,636.36 4479.48,636.36 4512.66,603.19 4850.11,603.19 4870.17,583.14 v2(5007.38,583.14)
REF4V1: R109.2 R110.1 U15.54 | length 1742.6
  Top Layer w7.87: v2(4964.27,1032.2) 4965.05,1032.98 U15.54@4995.57,1032.98 ; v2(5339.68,952.21) 5341.98,949.91 5341.98,917.92 5396.9,863 5411.14,863 R109.2@5413.64,860.5
  Power w7.87: v2(4061.24,649.89) 4061.24,651 4232.61,822.38 4432.56,822.38 4607.66,997.48 4727.59,997.48 4753.27,971.8 4928.82,971.8 4964.27,1007.25 v2(4964.27,1032.2)
  Bottom Layer w7.87: v2(4964.27,1032.2) 4964.52,1032.2 4979.82,1047.5 5075.33,1047.5 5089.83,1062 5213.25,1062 5227.75,1076.49 5278.76,1076.49 5314.97,1040.28 5314.97,976.92 v2(5339.68,952.21)
RSTn: R78.2 R159.1 U16.36 | length 838.1
  Top Layer w7.87: U16.36@4535.93,931.6 4559.26,931.6 4564.18,926.68 4565.16,926.68 4577.63,914.21 4577.63,909.93 4581.19,906.36 v2(4585.69,906.36)
  Bottom Layer w7.87: v2(4079.6,507.12) 4081.92,509.44 4081.92,518.91 4088.24,525.23 4088.24,678.09 4327.1,916.95 4575.02,916.95 4585.6,906.36 v2(4585.69,906.36)
SCLK_DAC: R147.2 U17.13 | length 673
  Top Layer w7.87: U17.13@3891.12,685.35 3891.85,684.62 3892.26,684.62 3892.26,665.27 v2(3912.08,645.45) ; v2(4028.1,547.27) 4320.18,547.27 4322.97,550.06 4434.04,550.06 4453.13,530.98 4453.13,517 R147.2@4461,509.13
  Bottom Layer w7.87: v2(3912.08,645.45) 3936.56,620.97 3949.09,620.97 3971.66,598.39 3971.66,584.29 4006.36,549.59 4025.78,549.59 v2(4028.1,547.27)
SCLKA: R65.2 R146.1 R152.1 TP7.1 U16.62 | length 1587.3
  Top Layer w7.87: v2(4232.3,506.37) R152.1@4232.3,507 ; v2(5094.41,843.8) 5097.69,843.8 5106.84,852.95 5144.28,852.95 U16.62@5146.16,854.83
  Bottom Layer w7.87: v2(4232.3,506.37) 4258.57,480.1 4340.23,480.1 v2(4365,504.87) 4366.68,503.19 4366.68,491.46 4391.19,466.96 4463.31,466.96 4486.65,490.29 4486.65,555.72 4516.14,585.21 4958.65,585.21 4978.39,604.95 5060.34,604.95 5093.44,638.04 TP7.1@5093.44,671.82 v2@5093.44,842.83 ; v2(4801.97,820.58) 4874.67,820.58 4886.06,809.19 5059.8,809.19 v2(5094.41,843.8)
SDI_DAC: R142.2 U17.14 | length 894.4
  Top Layer w7.87: U17.14@3891.12,705.04 3891.42,704.73 3903.25,704.73 v2(3960.79,647.2)
  Signal w7.87: v2(3998.61,605.88) 3998.61,521.12 4038.17,481.57 4216,481.57 4223.66,473.91 4588.3,473.91 v2(4623.52,509.13)
  Bottom Layer w7.87: v2(3960.79,647.2) 3960.79,645.45 3998.61,607.63 v2(3998.61,605.88)
SDIA: R66.2 R77.1 R141.1 TP8.1 U16.55 | length 1000
  Top Layer w7.87: v2(4428.38,524.88) 4428.38,506.57 R141.1@4429.15,505.8 ; v2(4955.82,678.04) 4956.2,678.43 U16.55@4956.2,767.23
  Bottom Layer w7.87: v2(4428.38,524.88) 4428.38,571.04 TP8.1@4513.2,655.86 4515.13,655.86 4522.46,663.19 4940.96,663.19 v2(4955.82,678.04) 4955.82,723.31 4905.23,773.9 4816.81,773.9 v2(4768.67,822.04)
SDO_DAC: R145.2 U17.15 | length 773.3
  Top Layer w7.87: U17.15@3891.12,724.72 3946.35,724.72 3947.92,726.29 3998.37,726.29 4003.42,721.24 v2(4006.7,721.24) ; v2(4036.39,583.14) 4053.95,565.58 4316.21,565.58 4316.44,565.81 4465.48,565.81 4493,538.28 R145.2@4493,509.13
  Bottom Layer w7.87: v2(4006.7,721.24) 4036.39,691.55 v2(4036.39,583.14)
SDOA: R67.2 R144.1 R179.2 TP9.1 U16.57 | length 1084
  Top Layer w7.87: R179.2@4834.68,820.58 4836.29,822.19 4882.96,822.19 R67.2@4884.57,823.8 4889.07,823.8 4895.97,830.7 4895.97,835.07 4902.89,841.99 4936.68,841.99 4937.98,840.69 4967.79,840.69 5007.24,801.24 5007.24,767.38 5007.71,766.9 5007.71,725.9 5016.55,717.06 v2(5016.55,714.53)
  Bottom Layer w7.87: v2(4395.24,495.72) 4397.56,493.4 4406.74,493.4 4412.82,487.32 4443.94,487.32 4470.9,514.28 4470.9,562.24 4509.62,600.96 4841.69,600.96 4872.42,631.69 4986.82,631.69 TP9.1@4987.31,632.19 5011.93,632.19 5016.55,636.8 v2(5016.55,714.53)
SDOB: R73.2 R150.1 U16.56 | length 1002.9
  Top Layer w7.87: R73.2@4919.78,822.68 4921.9,820.57 4950.21,820.57 4962.2,808.57 4964.76,808.57 4976.87,796.47 4976.87,795.49 4981.79,790.57 v2(4981.79,700.46)
  Signal w7.87: v2(4303.17,517.66) 4306.45,517.66 v2@4309.14,520.36
  Bottom Layer w7.87: v2(4303.17,517.66) 4304.33,517.66 4318.58,531.91 4390.5,531.91 4419.35,503.07 4437.42,503.07 4455.15,520.8 4455.15,568.76 4533.2,646.81 4641,646.81 4641.63,647.44 4968.76,647.44 4981.79,660.47 v2(4981.79,700.46)
SER1W: R91.1 R92.2 U16.45 | length 150
  Top Layer w7.87: R92.2@4631.96,674.88 R91.1@4681.96,674.88 4681.96,705.87 4700.3,724.21 U16.45@4700.3,767.23
Source_1: Q2_1.1 Q2_1.2 Q2_1.3 Q3_1.1 Q3_1.2 Q3_1.3 R21_1.2 R27_1.1 | length 348.1
  Top Layer w10: Q2_1.1@737.13,5151.69 843.35,5151.69 884.42,5192.76 1005.79,5192.76 1014.49,5201.46 1014.49,5213.96 1038.29,5237.76 R27_1.1@1042.23,5237.76
  other v1: 549.32,5153.85 742.58,5153.85 490,5164.8 674.24,5164.8 617.13,5171.64 795,5173.37 832.13,5174.74 530.78,5189.29 587.99,5206.89 490,5211.22 700.44,5211.22 789.26,5211.22 843.35,5211.22 632.02,5213.96
Source_2: Q2_2.1 Q2_2.2 Q2_2.3 Q3_2.1 Q3_2.2 Q3_2.3 R21_2.2 R27_2.1 | length 348.1
  Top Layer w10: Q2_2.1@2157.24,5155.28 2275.72,5155.28 2316.78,5196.34 2425.91,5196.34 2434.61,5205.04 2434.61,5217.54 2458.41,5241.34 R27_2.1@2462.35,5241.34
  other v1: 2096.01,5157.84 2050.55,5161.87 1965.92,5168.94 1916.6,5170.87 2263.47,5175.93 2214.16,5177.86 1906.6,5207.79 1948.58,5207.79 2117.04,5207.79 1992.18,5209.72 2048.62,5210.53 2204.16,5214.78 2246.14,5214.78
Source_3: Q2_3.1 Q2_3.2 Q2_3.3 Q3_3.1 Q3_3.2 Q3_3.3 R21_3.2 R27_3.1 | length 354.1
  Top Layer w20: Q2_3.1@3632.24,5155.28 3718.63,5155.28 3722.97,5159.62 3739.25,5159.62 3775.97,5196.34 3900.91,5196.34 3909.61,5205.04 3909.61,5227.81 3921.32,5239.53 3935.54,5239.53 R27_3.1@3937.35,5241.34
  other v1: 3670,5160 3739.63,5160 3577.74,5168.38 3451.52,5169.15 3402.2,5171.09 3530.6,5176.15 3392.2,5208.01 3434.18,5208.01 3602.64,5208.01 3477.77,5209.94 3534.22,5210.75 3689.75,5215 3731.73,5215
Source_4: Q2_4.1 Q2_4.2 Q2_4.3 Q3_4.1 Q3_4.2 Q3_4.3 R21_4.2 R27_4.1 | length 348.1
  Top Layer w20: Q2_4.1@5078.02,5148.44 5184.25,5148.44 5225.31,5189.5 5346.69,5189.5 5355.39,5198.2 5355.39,5210.7 5379.19,5234.5 R27_4.1@5383.13,5234.5
  other v1: 5083.82,5153.98 5125.8,5153.98 5169.39,5155.91 4891.78,5166.16 4842.47,5168.09 4970.86,5173.15 5023.41,5181.85 5123.58,5192.14 4832.47,5205.01 4874.45,5205.01 5042.91,5205.01 4918.04,5206.94 4974.49,5207.75
SW_1: C24_1.2 L1_1.1 Q1_1.1 Q1_1.2 Q1_1.3 Q4_1.5 Q4_1.6 Q4_1.7 Q4_1.8 Q4_1.9@788.03,3058.86 R2_1.2 R3_1.2 R42_1.2 U3_1.5 | length 77.5
  Top Layer w10: C24_1.2@792.13,2921.42 793.11,2921.42 810.67,2903.86 810.67,2860.39 811.46,2859.61 U3_1.5@818.54,2859.61
  other v1: 831.33,2997.83 711.1,3009.08 740.79,3009.08 769.92,3009.08 799.92,3009.08 738.21,3054.15 767.9,3054.15 797.03,3054.15 827.03,3054.15 857.03,3054.15 706.18,3095 735.87,3095 765,3095 795,3095 825,3095 855,3095 721.64,3135 751.32,3135 780.45,3135 810.45,3135 840.45,3135 677.56,3468.29 707.24,3468.29 736.38,3468.29 766.38,3468.29 796.38,3468.29 827.34,3468.29 857.03,3468.29 886.16,3468.29 916.16,3468.29 946.16,3468.29 981.18,3468.29 1010.87,3468.29 1040,3468.29 1070,3468.29 1100,3468.29 695.32,3515 725,3515 754.13,3515 784.13,3515 814.13,3515 847.22,3515 876.91,3515 906.04,3515 936.04,3515 966.04,3515 1000.32,3515 1030,3515 1059.13,3515 1089.13,3515 1119.13,3515
SW_2: C24_2.2 L1_2.1 Q1_2.1 Q1_2.2 Q1_2.3 Q4_2.5 Q4_2.6 Q4_2.7 Q4_2.8 Q4_2.9@2208.15,3062.44 R2_2.2 R3_2.2 R42_2.2 U3_2.5 | length 85
  Top Layer w10: C24_2.2@2212.24,2925 2215.93,2921.32 2215.93,2897.16 2230.61,2882.47 2230.61,2869.05 2231.85,2867.81 2231.85,2863.46 2232.13,2863.19 U3_2.5@2238.66,2863.19
  Bottom Layer w7.87: R2_2.2@2259.64,2977.67 v2(2259.64,2982.67) 2262.74,2982.67 R2_2.2@2262.99,2982.91
  other v1: 2132.08,3013.19 2161.77,3013.19 2190.9,3013.19 2220.9,3013.19 2250.9,3013.19 2159.19,3058.26 2188.88,3058.26 2218.01,3058.26 2248.01,3058.26 2278.01,3058.26 2127.16,3099.11 2156.85,3099.11 2185.98,3099.11 2215.98,3099.11 2245.98,3099.11 2275.98,3099.11 2142.62,3139.11 2172.3,3139.11 2201.44,3139.11 2231.44,3139.11 2261.44,3139.11 2106.25,3483.29 2135.93,3483.29 2165.07,3483.29 2195.07,3483.29 2225.07,3483.29 2256.03,3483.29 2285.72,3483.29 2314.85,3483.29 2344.85,3483.29 2374.85,3483.29 2409.87,3483.29 2439.56,3483.29 2468.69,3483.29 2498.69,3483.29 2528.69,3483.29 2124,3530 2153.69,3530 2182.82,3530 2212.82,3530 2242.82,3530 2275.91,3530 2305.6,3530 2334.73,3530 2364.73,3530 2394.73,3530 2429,3530 2458.69,3530 2487.82,3530 2517.82,3530 2547.82,3530
SW_3: C24_3.2 L1_3.1 Q1_3.1 Q1_3.2 Q1_3.3 Q4_3.5 Q4_3.6 Q4_3.7 Q4_3.8 Q4_3.9@3683.15,3062.44 R2_3.2 R3_3.2 R42_3.2 U3_3.5 | length 84.9
  Top Layer w10: C24_3.2@3687.24,2925 3694.42,2917.82 3694.42,2897.16 3705.61,2885.97 3705.61,2864.91 3707.34,2863.19 U3_3.5@3713.66,2863.19
  Bottom Layer w7.87: R2_3.2@3734.64,2977.67 3734.64,2982.67 3737.74,2982.67 R2_3.2@3737.99,2982.91
  other v1: 3615.16,3003.2 3644.84,3003.2 3673.98,3003.2 3703.98,3003.2 3733.98,3003.2 3642.27,3048.28 3671.95,3048.28 3701.09,3048.28 3731.09,3048.28 3761.09,3048.28 3610.24,3089.12 3639.92,3089.12 3669.06,3089.12 3699.06,3089.12 3729.06,3089.12 3759.06,3089.12 3625.69,3129.12 3655.38,3129.12 3684.51,3129.12 3714.51,3129.12 3744.51,3129.12 3610.23,3466.24 3639.92,3466.24 3669.05,3466.24 3699.05,3466.24 3729.05,3466.24 3760.02,3466.24 3789.7,3466.24 3818.83,3466.24 3848.83,3466.24 3878.83,3466.24 3913.85,3466.24 3943.54,3466.24 3972.67,3466.24 4002.67,3466.24 4032.67,3466.24 3627.99,3512.95 3657.67,3512.95 3686.81,3512.95 3716.81,3512.95 3746.81,3512.95 3779.89,3512.95 3809.58,3512.95 3838.71,3512.95 3868.71,3512.95 3898.71,3512.95 3932.99,3512.95 3962.67,3512.95 3991.81,3512.95 4021.81,3512.95 4051.81,3512.95
SW_4: C24_4.2 L1_4.1 Q1_4.1 Q1_4.2 Q1_4.3 Q4_4.5 Q4_4.6 Q4_4.7 Q4_4.8 Q4_4.9@5128.93,3055.6 R2_4.2 R3_4.2 R42_4.2 U3_4.5 | length 85.5
  Top Layer w10: C24_4.2@5133.02,2918.16 5134.01,2918.16 5147.71,2904.46 5147.71,2894.06 5151.39,2890.38 5151.39,2858.07 5153.11,2856.35 U3_4.5@5159.44,2856.35
  Bottom Layer w7.87: R2_4.2@5180.42,2970.83 5180.42,2975.83 5183.52,2975.83 R2_4.2@5183.77,2976.07
  other v1: 5068.4,2995.29 5098.09,2995.29 5127.22,2995.29 5163.46,2994.58 5187.22,2995.29 5095.51,3040.36 5125.2,3040.36 5154.33,3040.36 5184.33,3040.36 5214.33,3040.36 5063.48,3081.21 5093.17,3081.21 5122.3,3081.21 5152.3,3081.21 5182.3,3081.21 5212.3,3081.21 5078.94,3121.21 5108.62,3121.21 5137.76,3121.21 5167.76,3121.21 5197.76,3121.21 5037.98,3461.05 5067.66,3461.05 5096.8,3461.05 5126.8,3461.05 5156.8,3461.05 5187.77,3461.05 5217.45,3461.05 5246.58,3461.05 5276.58,3461.05 5306.58,3461.05 5341.6,3461.05 5371.29,3461.05 5400.42,3461.05 5430.42,3461.05 5460.42,3461.05 5055.74,3507.76 5085.42,3507.76 5114.55,3507.76 5144.55,3507.76 5174.55,3507.76 5207.64,3507.76 5237.33,3507.76 5266.46,3507.76 5296.46,3507.76 5326.46,3507.76 5360.74,3507.76 5390.42,3507.76 5419.55,3507.76 5449.55,3507.76 5479.55,3507.76
SYNCIN: J4.1 R137.2 | length 1622.3
  Top Layer w7.87: R137.2@4687,509.13 v2(4688.1,509.13)
  Signal w7.87: v2(4688.1,509.13) 4716.42,537.44 5023.71,537.44 5034.24,547.97 5939.32,547.97 J4.1@6189.56,798.21
TEST1: J13.100 TP11.1 | length 4615.4
  Top Layer w7.87: v2(3005,135) 3005,183.49 3125.86,304.35 3481.45,304.35 3530.07,255.73 3872.97,255.73 3920.6,208.09 3920.6,177.59 J13.100@3922.69,175.5
  Signal w7.87: v2(3005,135) 3107.5,237.5 3296.94,237.5 3349.3,185.15 3496.88,185.15 3532.99,221.26 4026.73,221.26 4061.24,186.75 4678.97,186.75 4695.44,203.22 4698.09,203.22 4743.61,248.74 4938.64,248.74 5024.89,335 6050,335 6217.27,502.27 6290.22,502.27 TP11.1@6303.42,515.46
TEST2: J13.102 TP12.1 | length 2498
  Top Layer w7.87: v2(3035,115) 3038.28,115 3049.13,125.85 3049.43,125.85 3055,131.41 3055,193.47 3146.53,285 3475,285 3523.55,236.45 3869.41,236.45 3887.23,218.63 3887.23,179.47 J13.102@3891.2,175.5
  Signal w7.87: TP12.1@1647.95,227.63 1653.56,222.02 1653.56,172.63 1716.19,110 2371.46,110 2374.64,113.19 3033.19,113.19 v2(3035,115)
TEST3: J13.104 TP13.1 | length 2411
  Top Layer w7.87: v2(3077.18,109.76) 3077.18,193.38 3148.8,265 3306.76,265 3382.48,189.28 3505.08,189.28 3511.86,196.07 3511.86,198.63 3533.43,220.19 3833.68,220.19 3853.8,200.08 3853.8,181.41 J13.104@3859.7,175.5
  Signal w7.87: TP13.1@1646.57,89.2 1647.67,88.1 3055.52,88.1 v2(3077.18,109.76)
V_HV: C1.1 C2.1 F1_1.2 F1_2.2 F1_3.2 F1_4.2 J1.1 J11.3 R157.2 T1.1 | length 3672.2
  Top Layer w7.87: J1.1@500.19,1550 J1.1@545,1550 ; J11.3@590,300 590,369.84 826.89,606.73 865.7,645.55 ; T1.1@781.29,1324.84 556.14,1550 J1.1@545,1550 ; T1.1@783.26,1322.88 802.2,1303.94 802.2,1274.87 865.7,1211.36 865.7,645.55 ; T1.1@785.38,1325 v2(781.45,1325) 780.92,1324.47 555.38,1550 J1.1@545,1550 ; v2(2273.14,535) 2256.46,551.69 2245.54,551.69 2229.78,567.44 2177.22,567.44 2165.12,555.33 2165.12,504.15 2154.59,493.62 2080.24,493.62 2065.47,478.85 1396.67,478.85 1396.23,479.29 1323.77,479.29 1323.69,479.21 1317.16,479.21 1150.82,645.55 865.7,645.55
  Bottom Layer w7.87: v2(2273.14,535) 2486.29,535 2500.11,521.18 v2(2503.36,521.18)
  other v1: 624.04,2095 653.73,2095 682.86,2095 712.86,2095 742.86,2095 772.86,2095 802.86,2095 4813.49,2103.85 4843.18,2103.85 4872.31,2103.85 4902.31,2103.85 4932.31,2103.85 4962.31,2103.85 4992.31,2103.85 3510.39,2105 3540.08,2105 3569.21,2105 3599.21,2105 3629.21,2105 3659.21,2105 3689.21,2105 2055.83,2110 2085.52,2110 2114.65,2110 2144.65,2110 2174.65,2110 2204.65,2110 2234.65,2110 621.7,2135.85 650.83,2135.85 680.83,2135.85 710.83,2135.85 740.83,2135.85 770.83,2135.85 4781.46,2144.7 4811.15,2144.7 4840.28,2144.7 4870.28,2144.7 4900.28,2144.7 4930.28,2144.7 4960.28,2144.7 3478.36,2145.85 3508.05,2145.85 3537.18,2145.85 3567.18,2145.85 3597.18,2145.85 3627.18,2145.85 3657.18,2145.85 2023.8,2150.85 2053.49,2150.85 2082.62,2150.85 2112.62,2150.85 2142.62,2150.85 2172.62,2150.85 2202.62,2150.85 607.47,2175.85 637.15,2175.85 666.29,2175.85 696.29,2175.85 726.29,2175.85 756.29,2175.85 4796.92,2184.7 4826.6,2184.7 4855.74,2184.7 4885.74,2184.7 4915.74,2184.7 4945.74,2184.7 4975.74,2184.7 3493.82,2185.85 3523.5,2185.85 3552.63,2185.85 3582.63,2185.85 3612.63,2185.85 3642.63,2185.85 3672.63,2185.85 2039.26,2190.85 2068.94,2190.85 2098.08,2190.85 2128.08,2190.85 2158.08,2190.85 2188.08,2190.85
  other v2: 95.19,1325 135.19,1325 175.19,1325 215.19,1325 701.45,1325 741.45,1325 95.19,1365 135.19,1365 175.19,1365 215.19,1365 781.45,1365 95.19,1405 135.19,1405 175.19,1405 215.19,1405 781.45,1405 95.19,1445 135.19,1445 175.19,1445 215.19,1445 95.19,1485 135.19,1485 175.19,1485 215.19,1485 95.19,1525 135.19,1525 175.19,1525 215.19,1525 95.19,1575 135.19,1575 175.19,1575 215.19,1575 95.19,1615 135.19,1615 175.19,1615 215.19,1615 95.19,1655 135.19,1655 175.19,1655 215.19,1655 95.19,1695 135.19,1695 175.19,1695 215.19,1695 781.45,1695 95.19,1735 135.19,1735 175.19,1735 215.19,1735 781.45,1735 95.19,1775 135.19,1775 175.19,1775 215.19,1775 701.45,1775 741.45,1775 781.45,1775
Vbat_ACN1: R100.1 R166.1 | length 1608.8
  Top Layer w7.87: R100.1@3852.41,854.83 3853.64,856.06 v2(3853.64,878.23) ; v2(4469.85,1383.88) 4470.28,1384.31 4484.51,1384.31 4573.52,1473.32 v2(4771.68,1473.32) ; v2(5056.78,1518.14) 5056.78,1488.22 R166.1@5060,1485
  Bottom Layer w7.87: v2(3853.64,878.23) 3854.29,878.23 3871.65,895.58 4121.9,895.58 4426.31,1199.99 4426.31,1340.34 v2(4469.85,1383.88) ; v2(4771.68,1473.32) 4774.97,1473.32 4782.22,1480.58 5019.22,1480.58 v2(5056.78,1518.14)
Vbat_ACN2: R101.1 R170.1 | length 1626.9
  Top Layer w7.87: R101.1@3820,855 3822.05,857.05 3822.05,878.27 v2(3822.95,879.17) ; v2(4485,1423.5) 4485,1426.78 4489.62,1431.41 4489.62,1433.97 4558.12,1502.47 4766.4,1502.47 v2(4767.06,1503.14) ; R170.1@4972.63,1495 v2(4972.63,1515)
  Bottom Layer w7.87: v2(3822.95,879.17) 3822.95,878.08 3844.61,856.42 4147.26,856.42 4450.97,1160.13 4450.97,1334.16 4491.66,1374.85 4491.66,1413.56 4485,1420.22 v2(4485,1423.5) ; v2(4767.06,1503.14) 4770.35,1503.14 4774.78,1498.7 4777.72,1498.7 4780.1,1496.33 4912.51,1496.33 4931.18,1515 v2(4972.63,1515)
Vbat_ACN3: R102.1 R174.1 | length 1540
  Top Layer w7.87: R102.1@3783.87,853.66 3786.12,855.91 3786.12,876.83 v2(3788.37,879.08) ; v2(4435.82,1410.04) 4448.03,1422.25 4448.03,1423.23 4549.09,1524.28 v2(4742.62,1524.28) ; v2(4903.47,1518.14) 4903.97,1517.64 4903.97,1495.5 R174.1@4904.47,1495
  Bottom Layer w7.87: v2(3788.37,879.08) 3791.65,879.08 3797.38,884.81 3797.74,884.81 3813.91,900.98 3841.76,900.98 4122.04,1181.27 4377.16,1181.27 4409.35,1213.46 4409.35,1350.53 4435.82,1377.01 v2(4435.82,1410.04) ; v2(4742.62,1524.28) 4745.9,1524.28 4750.8,1529.19 4810.04,1529.19 4821.09,1518.14 v2(4903.47,1518.14)
Vbat_ACN4: R103.1 R178.1 | length 1864.9
  Top Layer w7.87: v2(3702.22,819.53) 3703.61,818.14 3703.61,786.39 R103.1@3705,785 ; v2(4071.29,1560.29) 4165.9,1560.29 4288.86,1437.32 4439.85,1437.32 4553.53,1551 v2(4767.39,1551) ; R178.1@4834.12,1495 4834.12,1541.68 v2(4834.22,1541.78)
  Bottom Layer w7.87: v2(3702.22,819.53) 3704.54,821.85 3704.54,830.34 3790.93,916.73 3831.88,916.73 4041.72,1126.57 4041.72,1530.72 v2(4071.29,1560.29) ; v2(4767.39,1551) 4821.72,1551 4830.94,1541.78 v2(4834.22,1541.78)
Vbat_ACP1: R49_1.2 R72.1 | length 1136.3
  Top Layer w7.87: R72.1@5095,1485 5099.5,1485 5217.08,1602.58 v2(5729.35,1602.58) ; v2(6154.36,1668.43) R49_1.2@6154.37,1672.89
  Bottom Layer w7.87: v2(5729.35,1602.58) 5781.3,1654.52 6137.42,1654.52 6148.88,1665.99 6151.16,1665.99 v2@6151.65,1665.49
Vbat_ACP2: R49_2.2 R168.1 | length 953.6
  Top Layer w7.87: R168.1@5008.7,1495 5013.01,1495 5015.51,1497.5 5015.51,1522.02 5033.44,1539.95 5131.58,1539.95 5217.81,1626.18 5716.18,1626.18 5756.45,1666.45 5864.26,1666.45 5871.07,1673.26 R49_2.2@5871.07,1676.34
Vbat_ACP3: R49_3.2 R172.1 | length 738
  Top Layer w7.87: R172.1@4943.97,1495 4945.44,1496.47 4945.44,1532.38 4977.72,1564.67 5134.02,1564.67 5211.29,1641.93 5563.08,1641.93 5575.79,1654.64 5579.72,1654.64 5587.6,1662.51 R49_3.2@5587.6,1666.45
Vbat_ACP4: R49_4.2 R176.1 | length 546.4
  Top Layer w7.87: R176.1@4868.66,1495 4868.66,1530.14 4918.93,1580.42 5095.11,1580.42 5178.41,1663.72 5313.93,1663.72 R49_4.2@5321.48,1671.27
VbatN1: R35_1.2 R39_1.1 U15.10 U16.11 | length 1857.2
  Top Layer w7.87: v2(4814.98,1194.75) 4817.3,1197.07 4817.3,1205.48 4817.42,1205.59 U15.10@4817.42,1226.88 ; U16.11@4828.25,1377.47 4829.59,1376.12 4829.59,1312.83 v2(4830.94,1311.48) ; R39_1.1@6057.57,1876.79 6057.81,1876.79 6065.68,1884.66 6065.68,1928.61 v2(6063.84,1930.46)
  Signal w7.87: v2(4830.94,1311.48) 4830.94,1308.42 4883.35,1256.01 5054.03,1256.01 5378.78,1580.77 5781.37,1580.77 6063.84,1863.23 v2(6063.84,1930.46)
  Bottom Layer w7.87: v2@4817.81,1194.75 4817.3,1195.26 4817.3,1200.36 4830.94,1213.99 v2(4830.94,1311.48)
VbatN2: R35_2.2 R39_2.1 U15.12 U16.13 | length 1682.1
  Top Layer w7.87: U16.13@4777.07,1377.47 4778.54,1375.99 4778.54,1349.87 4779.36,1349.05 v2(4779.36,1316.97) ; v2(4783.49,1194.75) 4785.81,1197.07 4785.81,1205.48 4785.93,1205.59 U15.12@4785.93,1226.88 ; R39_2.1@5770.66,1885.9 5773.87,1885.9 5781.74,1893.77 5781.74,1912.02 5790.37,1920.64 v2(5790.37,1923.89)
  Signal w7.87: v2(4779.36,1316.97) 4776.08,1316.97 4762.74,1303.63 4746.05,1303.63 4744.31,1305.37 4743.7,1305.37 4730.93,1318.14 4730.93,1318.75 4725.89,1323.79 4725.89,1344.16 4767.05,1385.32 5120.32,1385.32 5495.75,1760.75 5681.81,1760.75 5790.37,1869.3 v2(5790.37,1923.89)
  Bottom Layer w7.87: v2@4779.36,1202.16 v2(4779.36,1316.97)
VbatN3: R35_3.2 R39_3.1 U15.14 U16.18 | length 1523.1
  Top Layer w7.87: v2(4651.53,1420.22) 4650.32,1419.01 4650.32,1378.68 U16.18@4649.11,1377.47 4651,1375.59 4651,1340.4 4698.86,1292.53 4718.89,1292.53 4754.43,1257 U15.14@4754.43,1226.88 ; R39_3.1@5481.67,1888.42 5484.5,1885.59 5488.94,1885.59 5492.87,1885.59 5499.69,1892.4 5499.69,1912.74 5510.83,1923.89 v2(5510.83,1926.6)
  Signal w7.87: v2@4655.47,1424.44 4655.47,1432.95 4686.51,1463.99 4750.17,1463.99 4762.65,1451.51 4863.61,1451.51 4904.66,1492.56 5154.51,1492.56 5241.8,1579.85 5241.8,1778.32 5411.37,1947.88 5489.54,1947.88 v2(5510.83,1926.6)
VbatN4: R35_4.2 R39_4.1 U15.16 U16.20 | length 1200.6
  Top Layer w7.87: U16.20@4597.93,1377.47 4599.82,1375.59 4599.82,1337.48 4710.41,1226.88 U15.16@4722.93,1226.88 ; R39_4.1@5219.86,1888.83 5223.8,1888.83 5230.61,1895.64 5230.61,1915.98 5241.76,1927.13 v2(5241.76,1929.83)
  Signal w7.87: v2(4594.52,1405.81) 4594.52,1496.11 4828.59,1730.18 5078.48,1730.18 5232.11,1883.81 5232.11,1919.16 5241.76,1928.81 v2(5241.76,1929.83)
VbatP1: R32_1.1 U4_1.4 U15.9 U16.12 | length 1845.5
  Top Layer w7.87: U16.12@4802.66,1377.47 4802.31,1377.13 4802.31,1299.13 v2(4801.97,1298.79) 4804.29,1296.47 4812.86,1296.47 4833.17,1276.16 U15.9@4833.17,1241.64 4833.17,1230.2 ; R32_1.1@6057.3,1837.57 6064.11,1844.39 6085.33,1844.39 6092.73,1851.79 6092.73,1885.9 v2(6094.95,1888.12)
  Signal w7.87: v2(4801.97,1298.79) 4860.49,1240.27 5061.45,1240.27 5386.2,1565.02 5798.86,1565.02 6094.95,1861.11 v2(6094.95,1888.12)
VbatP2: R32_2.1 U4_2.4 U15.11 U16.14 | length 1590
  Top Layer w7.87: U16.14@4751.48,1377.47 4752.11,1376.84 4752.11,1327.81 4755.06,1324.86 4755.06,1310.43 4801.67,1263.81 U15.11@4801.67,1226.88 ; R32_2.1@5770.99,1842.75 5774.93,1842.75 5790.59,1858.41 5813.52,1858.41 5819.41,1864.3 v2(5819.41,1889.46)
  Signal w7.87: v2(4752.74,1327.18) 4795.13,1369.57 5128.85,1369.57 5504.28,1745 5737.27,1745 5819.41,1827.15 v2(5819.41,1889.46)
VbatP3: R32_3.1 U4_3.4 U15.13 U16.17 | length 1519.2
  Top Layer w7.87: U16.17@4674.7,1377.47 4674.7,1347.98 v2(4674.48,1347.76) 4674.49,1344.47 4679.02,1339.94 4679.02,1337.2 4707.93,1308.28 4725.41,1308.28 4770.18,1263.52 U15.13@4770.18,1226.88 ; R32_3.1@5488.94,1850.59 5488.94,1852.23 5492.41,1855.7 5497.99,1855.7 5520.81,1878.53 5520.81,1890.11 v2(5523.11,1892.4)
  Signal w7.87: v2(4674.48,1347.76) 4676.8,1350.08 4676.8,1432.01 4693.03,1448.24 4743.65,1448.24 4756.13,1435.76 4870.32,1435.76 4911.37,1476.81 5161.03,1476.81 5260.43,1576.21 5260.43,1654.85 5260.06,1655.23 5260.06,1774.31 5354.74,1868.99 5462.76,1868.99 5498.55,1904.78 5510.72,1904.78 v2(5523.11,1892.4)
VbatP4: R32_4.1 U4_4.4 U15.15 U16.19 | length 1205.2
  Top Layer w7.87: v2(4623,1411) 4623.26,1410.74 4623.26,1377.73 4625.41,1375.59 4625.41,1343.72 4692.34,1276.79 4712.37,1276.79 4738.68,1250.47 U15.15@4738.68,1226.88 ; R32_4.1@5219.86,1853.83 5226.67,1860.64 5239.5,1860.64 5251.74,1872.87 5251.74,1893.34 v2(5254.03,1895.64)
  Signal w7.87: v2(4623,1411) 4623,1502.31 4835.11,1714.43 5094.41,1714.43 5254.03,1874.05 v2(5254.03,1895.64)
Vin: C94.1 J13.28 R143.2 | length 3485.8
  Top Layer w7.87: R143.2@2486.12,449.18 2486.29,449.01 v2(2486.29,444.98) ; v2(5182.54,75) J13.28@5182.54,175.5
  Bottom Layer w7.87: v2(2486.29,444.98) 2488.61,442.66 2488.61,433.09 2846.71,75 v2(5182.54,75) 5237.19,75 5441,278.81 v2(5441,461.88)
VIN_1: C3_1.1 C4_1.1 C5_1.1 C6_1.1 C9_1.1 C12_1.1 C13_1.1 C14_1.1 C18_1.1 F1_1.1 Q1_1.5 Q1_1.6 Q1_1.7 Q1_1.8 Q1_1.9@1061.85,3054.33 Q5_1.4 | length 2383.4
  Top Layer w7.87: Q5_1.4@1279.12,5142.76 v2(1279.12,5143.08)
  Bottom Layer w7.87: C14_1.1@1129.06,2909.72 1130.04,2909.72 1222.4,3002.08 1222.4,3141.96 1325,3244.56 1325,4766.1 1220,4871.1 1220,5083.96 v2(1279.12,5143.08)
  other v1: 903.94,2310.85 933.62,2310.85 962.76,2310.85 992.76,2310.85 1022.76,2310.85 1052.76,2310.85 1082.76,2310.85 615.51,2320 645.2,2320 674.33,2320 704.33,2320 734.33,2320 764.33,2320 794.33,2320 866.06,2350 905.87,2350 935,2350 965,2350 995,2350 1025,2350 1055,2350 583.48,2360.85 613.17,2360.85 642.3,2360.85 672.3,2360.85 702.3,2360.85 732.3,2360.85 762.3,2360.85 598.94,2400.85 628.62,2400.85 657.76,2400.85 687.76,2400.85 717.76,2400.85 747.76,2400.85 777.76,2400.85 1122.31,2536.2 1080,2550 1122.31,2562.86 1080,2576.66 1122.56,2588.51 1080.25,2602.31 1122.56,2611.94 1080.25,2625.74 1122.56,2640 1080.25,2653.8 1082.76,2683.18 1120.44,2692 1082.76,2709.85 1126.97,2727.51 1083.01,2735.5 1125.82,2757.04 1083.01,2758.92 1125.82,2785.1 1083.01,2786.73 1101.69,2820.24 1134.87,2826.1 1101.69,2846.9 1134.87,2852.76 1116.49,2908.27 991.09,2988.61 1020.78,2988.61 1049.91,2988.61 1079.91,2988.61 1109.91,2988.61 1018.2,3033.68 1047.89,3033.68 1077.02,3033.68 1107.02,3033.68 1137.02,3033.68 986.17,3074.53 1015.86,3074.53 1044.99,3074.53 1074.99,3074.53 1104.99,3074.53 1134.99,3074.53 1001.63,3114.53 1031.31,3114.53 1060.44,3114.53 1090.44,3114.53 1120.44,3114.53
